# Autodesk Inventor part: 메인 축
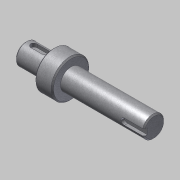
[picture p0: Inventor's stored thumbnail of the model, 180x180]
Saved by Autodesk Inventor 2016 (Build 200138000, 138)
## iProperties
Created: 2016-04
Part Number: 메인 축
Document SubType Name: Modeling
Designer: mdu
Density: 7.86 g/cm^3
Mass: 230.24 g
Surface Area: 74.3518 cm^2
Volume: 29.2926 cm^3
Material: 강철, 연강
Appearance: 금속-강(스테인리스, 브러시됨)
Author: mdu
Revision Number: 1
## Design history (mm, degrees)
sketch "스케치1"
  geometry: L1 (10.497, -57.5)-(112.497, -57.5); L2 (10.497, -66)-(32.497, -66); L3 (32.497, -72.5)-(46.5, -72.5); L4 (46.5, -66)-(112.497, -66); L5 (112.497, -66)-(112.497, -57.5); L6 (10.497, -66)-(10.497, -57.5); L7 (46.5, -69.749)-(46.5, -45.251) reference; L8 (46.5, -72.5)-(46.5, -66); L9 (32.497, -72.5)-(32.497, -66); L10 (32.497, -35)-(32.497, -80) reference; 3 further points
  constraints: 16 end point, 3 point on line, 2 parallel, 2 perpendicular, 1 collinear, 1 horizontal, 1 midpoint
  dimensions: "d0" = 17 diameter of L4 L1; "d1" = 30 diameter of L3 L1; "d2" = 22 distance of L2.start L2.end; "d3" = 65.99692 distance of L4.start L4.end (derived); "d5" = 17 diameter of L2 L1; "d19" = 80 distance between parallel lines of L5 L9
revolve "회전1" sketch "스케치1" stored, may be unused: angle "d4" = 90 deg
chamfer "모따기1" distance "d6" = 1; stored, may be unused: second distance "d7" = 2, angle "d8" = 45 deg
node "작업 평면1"
sketch "스케치2"
  geometry: L1 (-11, -7.5)-(-11, 7.5) reference; L2 (-4.5, 2.5)-(4.5, 2.5); L3 (4.5, -2.5)-(-4.5, -2.5); A1 r 2.5 centre (4.5, 0) between (4.5, -2.5) and (4.5, 2.5); A2 r 2.5 centre (-4.5, 0) between (-4.5, 2.5) and (-4.5, -2.5); 2 further points
  constraints: 4 end point, 4 point on circle, 4 tangent, 2 centre point, 1 horizontal alignment, 1 midpoint, 1 parallel, 1 perpendicular
  dimensions: "d9" = 5 distance between parallel lines of L3 L2; "d10" = 14 dimension on A1 A2; "d11" = 4 distance edge to line of A2 L1
extrude "돌출1" cut sketch "스케치2" distance "d12" = 3; taper "d13" = 0 deg
node "작업 평면2"
sketch "스케치3"
  geometry: L1 (32.998, 7.5)-(32.998, -7.5) reference; L2 (32.998, 2.5)-(17.498, 2.5); L3 (17.498, -2.5)-(32.998, -2.5); A1 r 2.5 centre (17.498, 0) between (17.498, 2.5) and (17.498, -2.5); 2 further points
  constraints: 4 end point, 2 perpendicular, 2 point on circle, 2 point on line, 2 tangent, 1 centre point, 1 horizontal alignment, 1 midpoint
  dimensions: "d14" = 5 distance between parallel lines of L3 L2; "d15" = 18 dimension on A1 L1
extrude "돌출2" cut sketch "스케치3" distance "d16" = 3; taper "d17" = 0 deg
node "솔리드1"
node "참조4"
node "참조5"
